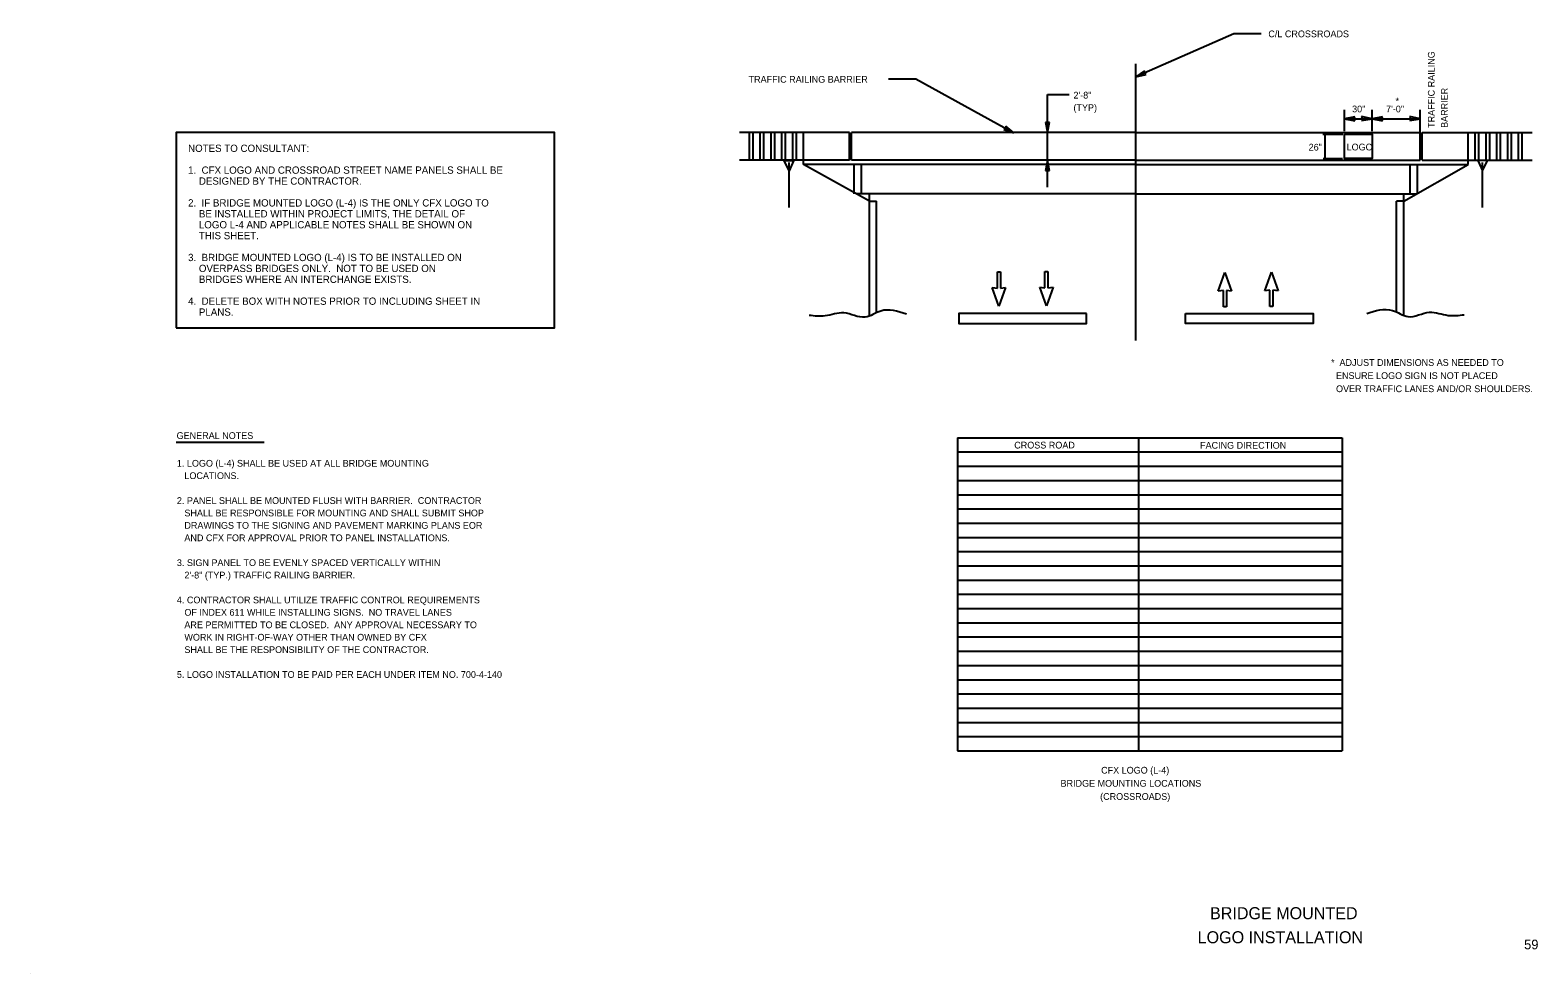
# Model space of a CAD drawing. Extents: x 53062 to 53689, y 9298 to 9690.
import ezdxf

# ---------------------------------------------------------------- set-up
doc = ezdxf.new("R2010")
doc.units = 0
for name, color, linetype in [('AdhocPoint_dp', 7, 'Continuous'), ('Bridge', 7, 'Continuous'), ('CLConst_dp', 7, 'Continuous'), ('Concrete', 7, 'Continuous'), ('DimLines_dp', 7, 'Continuous'), ('DirArrowsPavt', 7, 'Continuous'), ('Grass', 7, 'Continuous'), ('SignPanel', 7, 'Continuous'), ('TextAlert', 7, 'Continuous'), ('TextLabel', 7, 'Continuous'), ('TextMisc', 7, 'Continuous'), ('TextNotes', 7, 'Continuous'), ('TextShtNo', 7, 'Continuous'), ('TextTables', 7, 'Continuous')]:
    doc.layers.add(name, color=color, linetype=linetype)

msp = doc.modelspace()

# ---------------------------------------------------------------- linework, layer by layer
at = {"layer": 'AdhocPoint_dp'}
msp.add_line((53062.39, 9298.05), (53062.39, 9298.05), dxfattribs=at)
at = {"layer": 'Bridge'}
for p, q in [((53402.74, 9647.53), (53357.08, 9647.53)), ((53361.17, 9636.03), (53361.17, 9647.53)), ((53362.67, 9636.03), (53362.67, 9647.53)), ((53365.67, 9636.03), (53365.67, 9647.53)), ((53367.17, 9636.03), (53367.17, 9647.53)), ((53370.17, 9636.03), (53370.17, 9647.53)), ((53371.67, 9636.03), (53371.67, 9647.53)), ((53374.67, 9636.03), (53374.67, 9647.53)), ((53376.17, 9636.03), (53376.17, 9647.53)), ((53379.17, 9636.03), (53379.17, 9647.53)), ((53380.67, 9636.03), (53380.67, 9647.53)), ((53383.67, 9634.25), (53383.67, 9647.53)), ((53402.74, 9636.03), (53402.74, 9647.53)), ((53403.52, 9636.03), (53403.52, 9647.53)), ((53521.67, 9647.53), (53403.52, 9647.53)), ((53521.67, 9647.53), (53639.83, 9647.53)), ((53639.83, 9636.03), (53639.83, 9647.53)), ((53640.6, 9636.03), (53640.6, 9647.53)), ((53640.6, 9647.53), (53686.26, 9647.53)), ((53659.67, 9634.25), (53659.67, 9647.53)), ((53662.67, 9636.03), (53662.67, 9647.53)), ((53664.17, 9636.03), (53664.17, 9647.53)), ((53667.17, 9636.03), (53667.17, 9647.53)), ((53668.67, 9636.03), (53668.67, 9647.53)), ((53671.67, 9636.03), (53671.67, 9647.53)), ((53673.17, 9636.03), (53673.17, 9647.53)), ((53676.17, 9636.03), (53676.17, 9647.53)), ((53677.67, 9636.03), (53677.67, 9647.53)), ((53680.67, 9636.03), (53680.67, 9647.53)), ((53682.17, 9636.03), (53682.17, 9647.53)), ((53402.74, 9636.03), (53357.08, 9636.03)), ((53377.61, 9631.66), (53375.56, 9636.01)), ((53375.56, 9636.01), (53379.15, 9636.01)), ((53379.41, 9635.76), (53377.61, 9631.66)), ((53377.63, 9616.47), (53377.63, 9635.17)), ((53379.15, 9636.01), (53379.41, 9635.76)), ((53411, 9619.07), (53383.67, 9634.25)), ((53484.95, 9634.25), (53383.67, 9634.25)), ((53521.67, 9636.03), (53403.52, 9636.03)), ((53404.67, 9622.08), (53404.67, 9634.25)), ((53407.67, 9622.08), (53407.67, 9634.25)), ((53521.67, 9634.25), (53485.02, 9634.25)), ((53521.67, 9636.03), (53639.83, 9636.03)), ((53521.67, 9634.25), (53659.67, 9634.25)), ((53632.99, 9619.07), (53659.67, 9634.25)), ((53635.67, 9622.08), (53635.67, 9634.25)), ((53638.67, 9622.3), (53638.67, 9634.25)), ((53640.6, 9636.03), (53686.26, 9636.03)), ((53664.19, 9635.98), (53663.93, 9635.73)), ((53663.93, 9635.73), (53665.72, 9631.63)), ((53667.77, 9635.98), (53664.19, 9635.98)), ((53665.72, 9631.63), (53667.77, 9635.98)), ((53665.72, 9616.47), (53665.72, 9635.17)), ((53521.99, 9622.08), (53405.58, 9622.08)), ((53410.99, 9571.37), (53410.99, 9622.08)), ((53521.99, 9622.08), (53638.28, 9622.08)), ((53632.99, 9619.08), (53632.99, 9622.08)), ((53411, 9619.07), (53413.99, 9619.08)), ((53413.99, 9573.1), (53413.99, 9619.08)), ((53629.99, 9573.36), (53629.99, 9619.08)), ((53632.99, 9619.07), (53629.99, 9619.08)), ((53632.99, 9571.63), (53632.99, 9619.08))]:
    msp.add_line(p, q, dxfattribs=at)
at = {"layer": 'CLConst_dp'}
msp.add_line((53521.67, 9561.12), (53521.67, 9676.08), dxfattribs=at)
at = {"layer": 'Concrete'}
for points in [[(53501.23, 9572.38), (53448.21, 9572.38), (53448.21, 9568.28), (53501.23, 9568.28)], [(53542.25, 9572.38), (53595.27, 9572.38), (53595.27, 9568.28), (53542.25, 9568.28)]]:
    msp.add_lwpolyline(points, close=True, dxfattribs=at)
at = {"layer": 'DimLines_dp'}
for p, q in [((53484.98, 9663.31), (53494.03, 9663.31)), ((53484.98, 9647.58), (53484.98, 9663.31)), ((53608.28, 9648.18), (53608.28, 9657.05)), ((53619.79, 9648.18), (53619.79, 9657.05)), ((53639.83, 9647.53), (53639.83, 9657.05)), ((53484.98, 9651.6), (53484.17, 9651.93)), ((53484.17, 9651.93), (53484.98, 9647.58)), ((53484.98, 9651.6), (53484.17, 9651.93)), ((53484.17, 9651.93), (53484.98, 9647.58)), ((53484.98, 9647.58), (53485.82, 9651.93)), ((53485.82, 9651.93), (53484.98, 9651.6)), ((53484.98, 9647.58), (53485.82, 9651.93)), ((53485.82, 9651.93), (53484.98, 9651.6)), ((53612.63, 9654.12), (53608.28, 9653.32)), ((53612.63, 9654.12), (53608.28, 9653.32)), ((53608.28, 9653.32), (53619.79, 9653.32)), ((53608.28, 9653.32), (53612.63, 9652.48)), ((53608.28, 9653.32), (53612.63, 9652.48)), ((53612.3, 9653.32), (53612.63, 9654.12)), ((53612.3, 9653.32), (53612.63, 9654.12)), ((53612.63, 9652.48), (53612.3, 9653.32)), ((53612.63, 9652.48), (53612.3, 9653.32)), ((53619.79, 9653.32), (53615.44, 9654.16)), ((53615.44, 9654.16), (53615.77, 9653.32)), ((53619.79, 9653.32), (53615.44, 9654.16)), ((53615.44, 9654.16), (53615.77, 9653.32)), ((53615.77, 9653.32), (53615.44, 9652.51)), ((53615.44, 9652.51), (53619.79, 9653.32)), ((53615.77, 9653.32), (53615.44, 9652.51)), ((53615.44, 9652.51), (53619.79, 9653.32)), ((53624.14, 9654.12), (53619.79, 9653.32)), ((53624.14, 9654.12), (53619.79, 9653.32)), ((53619.79, 9653.32), (53639.83, 9653.32)), ((53619.79, 9653.32), (53624.14, 9652.48)), ((53619.79, 9653.32), (53624.14, 9652.48)), ((53623.81, 9653.32), (53624.14, 9654.12)), ((53623.81, 9653.32), (53624.14, 9654.12)), ((53624.14, 9652.48), (53623.81, 9653.32)), ((53624.14, 9652.48), (53623.81, 9653.32)), ((53639.83, 9653.32), (53635.48, 9654.16)), ((53635.48, 9654.16), (53635.81, 9653.32)), ((53635.81, 9653.32), (53635.48, 9652.51)), ((53635.48, 9652.51), (53639.83, 9653.32)), ((53484.98, 9634.25), (53484.98, 9647.58)), ((53599.29, 9646.83), (53607.63, 9646.83)), ((53600.31, 9636.49), (53600.31, 9646.94)), ((53484.98, 9636.03), (53484.14, 9631.68)), ((53484.14, 9631.68), (53484.98, 9632.01)), ((53484.98, 9624.91), (53484.98, 9636.03)), ((53485.79, 9631.68), (53484.98, 9636.03)), ((53484.98, 9632.01), (53485.79, 9631.68)), ((53599.49, 9636.75), (53607.58, 9636.75))]:
    msp.add_line(p, q, dxfattribs=at)
at = {"layer": 'DirArrowsPavt'}
for p, q in [((53464.18, 9589.7), (53465.42, 9589.7)), ((53464.18, 9582.95), (53464.18, 9589.7)), ((53465.42, 9589.7), (53465.42, 9582.95)), ((53483.9, 9589.83), (53485.15, 9589.83)), ((53483.9, 9583.08), (53483.9, 9589.83)), ((53485.15, 9589.83), (53485.15, 9583.08)), ((53555.92, 9581.69), (53558.66, 9589.42)), ((53558.66, 9589.42), (53561.41, 9581.69)), ((53575.25, 9581.82), (53578, 9589.55)), ((53578, 9589.55), (53580.75, 9581.82)), ((53464.8, 9575.45), (53462.05, 9583.18)), ((53462.05, 9583.18), (53464.18, 9582.95)), ((53467.55, 9583.18), (53464.8, 9575.45)), ((53465.42, 9582.95), (53467.55, 9583.18)), ((53484.52, 9575.58), (53481.77, 9583.31)), ((53481.77, 9583.31), (53483.9, 9583.08)), ((53487.27, 9583.31), (53484.52, 9575.58)), ((53485.15, 9583.08), (53487.27, 9583.31)), ((53558.04, 9581.92), (53555.92, 9581.69)), ((53558.04, 9575.17), (53558.04, 9581.92)), ((53561.41, 9581.69), (53559.29, 9581.92)), ((53559.29, 9581.92), (53559.29, 9575.17)), ((53577.38, 9582.05), (53575.25, 9581.82)), ((53577.38, 9575.3), (53577.38, 9582.05)), ((53580.75, 9581.82), (53578.63, 9582.05)), ((53578.63, 9582.05), (53578.63, 9575.3)), ((53559.29, 9575.17), (53558.04, 9575.17)), ((53578.63, 9575.3), (53577.38, 9575.3))]:
    msp.add_line(p, q, dxfattribs=at)
at = {"layer": 'Grass'}
for points in [[(53426.44, 9572.12), (53415.68, 9573.4), (53409.28, 9570.84), (53400.31, 9572.64), (53392.63, 9571.35), (53385.97, 9571.61)], [(53617.55, 9572.38), (53628.31, 9573.66), (53634.71, 9571.09), (53643.68, 9572.89), (53651.36, 9571.61), (53658.02, 9571.86)]]:
    msp.add_spline(points, degree=3, dxfattribs=at)
at = {"layer": 'SignPanel'}
msp.add_lwpolyline([(53608.28, 9646.83), (53619.78, 9646.83), (53619.78, 9636.75), (53608.28, 9636.75)], close=True, dxfattribs=at)
at = {"layer": 'TextAlert'}
msp.add_lwpolyline([(53122.98, 9566.47), (53280.25, 9566.47), (53280.25, 9647.53), (53122.98, 9647.53)], close=True, dxfattribs=at)
at = {"layer": 'TextLabel'}
for p, q in [((53562.43, 9688.6), (53521.67, 9670.67)), ((53573.7, 9688.6), (53562.43, 9688.6)), ((53418.98, 9669.81), (53430.25, 9669.81)), ((53430.25, 9669.81), (53471, 9647.4)), ((53525.33, 9673.17), (53521.67, 9670.67)), ((53521.67, 9670.67), (53525.99, 9671.66)), ((53525.35, 9672.29), (53525.33, 9673.17)), ((53525.99, 9671.66), (53525.35, 9672.29)), ((53467.48, 9649.34), (53466.8, 9648.79)), ((53467.48, 9649.34), (53466.8, 9648.79)), ((53466.8, 9648.79), (53471, 9647.4)), ((53466.8, 9648.79), (53471, 9647.4)), ((53467.6, 9650.23), (53467.48, 9649.34)), ((53467.6, 9650.23), (53467.48, 9649.34)), ((53471, 9647.4), (53467.6, 9650.23)), ((53471, 9647.4), (53467.6, 9650.23))]:
    msp.add_line(p, q, dxfattribs=at)
at = {"layer": 'TextNotes'}
msp.add_line((53122.98, 9518.92), (53159.57, 9518.92), dxfattribs=at)
at = {"layer": 'TextTables'}
for p, q in [((53447.62, 9520.76), (53607.31, 9520.76)), ((53447.62, 9520.76), (53447.62, 9390.7)), ((53522.91, 9390.7), (53522.91, 9520.76)), ((53607.31, 9520.76), (53607.31, 9390.7)), ((53447.62, 9514.85), (53607.31, 9514.85)), ((53447.62, 9508.94), (53607.31, 9508.94)), ((53447.62, 9503.03), (53607.31, 9503.03)), ((53447.62, 9497.11), (53607.31, 9497.11)), ((53447.63, 9491.2), (53607.31, 9491.2)), ((53447.62, 9485.29), (53607.31, 9485.29)), ((53447.62, 9479.38), (53607.31, 9479.38)), ((53447.62, 9473.47), (53607.31, 9473.47)), ((53447.62, 9467.56), (53607.31, 9467.56)), ((53447.62, 9461.64), (53607.31, 9461.64)), ((53447.62, 9455.73), (53607.31, 9455.73)), ((53447.62, 9449.82), (53607.31, 9449.82)), ((53447.62, 9443.91), (53607.31, 9443.91)), ((53447.62, 9437.99), (53607.31, 9437.99)), ((53447.62, 9432.08), (53607.31, 9432.08)), ((53447.62, 9426.17), (53607.31, 9426.17)), ((53447.62, 9420.26), (53607.31, 9420.26)), ((53447.62, 9414.35), (53607.31, 9414.35)), ((53447.62, 9408.43), (53607.31, 9408.43)), ((53447.62, 9402.52), (53607.31, 9402.52)), ((53447.62, 9396.61), (53607.31, 9396.61)), ((53447.62, 9390.7), (53607.31, 9390.7))]:
    msp.add_line(p, q, dxfattribs=at)

# ---------------------------------------------------------------- texts
at = {"layer": 'DimLines_dp'}
for s, p in [('2\'-8"', (53495.76, 9661.68)), ('(TYP)', (53495.76, 9656.51)), ('30"', (53611.5, 9655.96)), ('7\'-0"', (53625.6, 9655.95)), ('*', (53629.53, 9659.27)), ('26"', (53593.45, 9640.07))]:
    msp.add_text(s, height=2.8, dxfattribs=at).set_placement(p)
at = {"layer": 'TextAlert'}
for s, p in [('NOTES TO CONSULTANT:', (53127.98, 9639.51)), ('1.  CFX LOGO AND CROSSROAD STREET NAME PANELS SHALL BE', (53127.98, 9630.44)), ('    DESIGNED BY THE CONTRACTOR.', (53127.98, 9625.9)), ('2.  IF BRIDGE MOUNTED LOGO (L-4) IS THE ONLY CFX LOGO TO', (53127.98, 9616.83)), ('    BE INSTALLED WITHIN PROJECT LIMITS, THE DETAIL OF', (53127.98, 9612.29)), ('    LOGO L-4 AND APPLICABLE NOTES SHALL BE SHOWN ON', (53127.98, 9607.76)), ('    THIS SHEET.', (53127.98, 9603.22)), ('3.  BRIDGE MOUNTED LOGO (L-4) IS TO BE INSTALLED ON', (53127.98, 9594.15)), ('    OVERPASS BRIDGES ONLY.  NOT TO BE USED ON', (53127.98, 9589.61)), ('    BRIDGES WHERE AN INTERCHANGE EXISTS.', (53127.98, 9585.08)), ('4.  DELETE BOX WITH NOTES PRIOR TO INCLUDING SHEET IN', (53127.98, 9576)), ('    PLANS.', (53127.98, 9571.47))]:
    msp.add_text(s, height=3.024, dxfattribs=at).set_placement(p)
at = {"layer": 'TextLabel'}
for s, p in [('C/L CROSSROADS', (53576.71, 9687.15)), ('TRAFFIC RAILING BARRIER', (53360.81, 9668.26)), ('LOGO ', (53609.21, 9640.13))]:
    msp.add_text(s, height=2.8, dxfattribs=at).set_placement(p)
for s, p in [('TRAFFIC RAILING ', (53645.79, 9649.49)), ('BARRIER', (53651.25, 9649.49))]:
    msp.add_text(s, height=2.8, rotation=90, dxfattribs=at).set_placement(p)
at = {"layer": 'TextMisc'}
for s, p in [('     BRIDGE MOUNTED     ', (53543.2, 9320.75)), ('   LOGO INSTALLATION    ', (53541.77, 9310.75))]:
    msp.add_text(s, height=5, rotation=360, dxfattribs=at).set_placement(p)
at = {"layer": 'TextNotes'}
for s, p in [('*  ADJUST DIMENSIONS AS NEEDED TO', (53602.74, 9550.62)), ('  ENSURE LOGO SIGN IS NOT PLACED', (53602.74, 9545.17)), ('  OVER TRAFFIC LANES AND/OR SHOULDERS.', (53602.74, 9539.71)), ('GENERAL NOTES', (53123.23, 9520.26)), ('1. LOGO (L-4) SHALL BE USED AT ALL BRIDGE MOUNTING', (53123.34, 9508.76)), ('   LOCATIONS.', (53123.34, 9503.6)), ('2. PANEL SHALL BE MOUNTED FLUSH WITH BARRIER.  CONTRACTOR', (53123.34, 9493.27)), ('   SHALL BE RESPONSIBLE FOR MOUNTING AND SHALL SUBMIT SHOP', (53123.34, 9488.11)), ('   DRAWINGS TO THE SIGNING AND PAVEMENT MARKING PLANS EOR', (53123.34, 9482.95)), ('   AND CFX FOR APPROVAL PRIOR TO PANEL INSTALLATIONS.', (53123.34, 9477.79)), ('3. SIGN PANEL TO BE EVENLY SPACED VERTICALLY WITHIN ', (53123.34, 9467.46)), ('   2\'-8" (TYP.) TRAFFIC RAILING BARRIER.', (53123.34, 9462.3)), ('4. CONTRACTOR SHALL UTILIZE TRAFFIC CONTROL REQUIREMENTS', (53123.34, 9451.98)), ('   ARE PERMITTED TO BE CLOSED.  ANY APPROVAL NECESSARY TO ', (53123.34, 9441.65)), ('   OF INDEX 611 WHILE INSTALLING SIGNS.  NO TRAVEL LANES ', (53123.34, 9446.82)), ('   WORK IN RIGHT-OF-WAY OTHER THAN OWNED BY CFX', (53123.34, 9436.49)), ('   SHALL BE THE RESPONSIBILITY OF THE CONTRACTOR.', (53123.34, 9431.33)), ('5. LOGO INSTALLATION TO BE PAID PER EACH UNDER ITEM NO. 700-4-140', (53123.34, 9421.01))]:
    msp.add_text(s, height=2.8, dxfattribs=at).set_placement(p)
at = {"layer": 'TextShtNo'}
msp.add_text('59', height=4, rotation=360, dxfattribs=at).set_placement((53682.96, 9308.25))
at = {"layer": 'TextTables'}
for s, p in [('CROSS ROAD', (53471.16, 9516.3)), ('FACING DIRECTION', (53548.35, 9516.22)), ('CFX LOGO (L-4)', (53507.25, 9381.24)), ('BRIDGE MOUNTING LOCATIONS ', (53490.39, 9375.79)), ('(CROSSROADS)', (53506.83, 9370.33))]:
    msp.add_text(s, height=2.8, dxfattribs=at).set_placement(p)

doc.saveas('drawing.dxf')
